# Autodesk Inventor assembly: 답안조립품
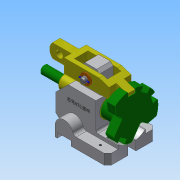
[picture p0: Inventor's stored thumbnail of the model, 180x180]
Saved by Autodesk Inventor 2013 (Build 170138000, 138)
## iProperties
Created: 2016-11
Part Number: 답안조립품
Document SubType Name: Assembly
Designer: Administrator
Author: Administrator
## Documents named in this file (8)
- C:\Users\Administrator\Desktop\461108V1030\답안조립품.iam
- C:\Users\Administrator\Desktop\461108V1030\본체.ipt
- C:\Users\Administrator\Desktop\461108V1030\부시.ipt
- C:\Users\Administrator\Desktop\461108V1030\분할대.ipt
- C:\Users\Administrator\Desktop\461108V1030\분할축.ipt
- C:\Users\Administrator\Desktop\461108V1030\와셔.ipt
- C:\Users\Administrator\Desktop\461108V1030\원통형핀.ipt
- C:\Users\Administrator\Desktop\461108V1030\클레비스핀.ipt
